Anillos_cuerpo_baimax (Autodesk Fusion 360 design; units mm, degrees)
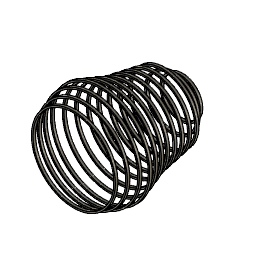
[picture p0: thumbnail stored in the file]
part number: 2026-07-18-00-39-53-117
parameter "d_1" = 112
parameter "d_1_int" = 108.5 (= "d_1 - 3.5 mm")
parameter "h_1" = -10
parameter "d_2" = 108.5
parameter "d_2_int" = 105 (= "d_2 - 3.5 mm")
parameter "h_2" = 10
parameter "h_3" = -20
parameter "h_4" = 20
parameter "h_5" = -30
parameter "h_6" = 30
parameter "h_7" = 40
parameter "d_3" = 105 (= "d_2_int")
parameter "d_3_int" = 101.5 (= "d_3 - 3.5 mm")
parameter "d_4" = 101.5 (= "d_3_int")
parameter "d_4_int" = 98 (= "d_4 - 3.5 mm")
parameter "d_5" = 98 (= "d_4_int")
parameter "d_5_int" = 94.5 (= "d_5 - 3.5 mm")
parameter "d_6" = 94.5 (= "d_5_int")
parameter "d_6_int" = 91 (= "d_6 - 3.5 mm")
parameter "d_7" = 91 (= "d_6_int")
parameter "d_7_int" = 87.5 (= "d_7 - 3.5 mm")
parameter "d_8" = 87.5 (= "d_7_int")
parameter "d_8_int" = 84 (= "d_8 - 3.5 mm")
parameter "h_8" = 50
parameter "h_9" = 60
parameter "h_10" = 70
parameter "h_11" = 110
parameter "h_12" = 120
parameter "h_13" = 130
parameter "h_14" = 140
parameter "h_15" = 80
parameter "d_9" = 84 (= "d_8_int")
parameter "d_9_int" = 80.5 (= "d_9 - 3.5 mm")
parameter "d_10" = 80.5 (= "d_9_int")
parameter "d_10_int" = 77 (= "d_10 - 3.5 mm")
parameter "d_11" = 77 (= "d_10_int")
parameter "d_11_int" = 73.5 (= "d_11 - 3.5 mm")
parameter "d_12" = 73.5 (= "d_11_int")
parameter "d_12_int" = 70 (= "d_12 - 3.5 mm")
parameter "d_13" = 70 (= "d_12_int")
parameter "d_13_int" = 66.5 (= "d_13 - 3.5 mm")
parameter "d_14" = 66.5 (= "d_13_int")
parameter "d_14_int" = 63 (= "d_14 - 3.5 mm")
parameter "d_15" = 63 (= "d_14_int")
parameter "d_15_int" = 59.5 (= "d_15 - 3.5 mm")
parameter "d_16" = 59.5 (= "d_15_int")
parameter "d_16_int" = 56 (= "d_16 - 3.5 mm")
parameter "h_16" = 160
parameter "h_17" = 170
parameter "h_18" = 180
parameter "h_19" = 90
parameter "h_20" = 200
parameter "d_17" = 56 (= "d_16_int")
parameter "d_17_int" = 52.5 (= "d_17 - 3.5 mm")
parameter "d_18" = 52.5 (= "d_17_int")
parameter "d_18_int" = 49 (= "d_18 - 3.5 mm")
parameter "d_19" = 49 (= "d_18_int")
parameter "d_19_int" = 45.5 (= "d_19 - 3.5 mm")
parameter "d_20" = 45.5 (= "d_19_int")
parameter "d_20_int" = 42 (= "d_20 - 3.5 mm")
parameter "d_21" = 42 (= "d_20_int")
parameter "d_21_int" = 38.5 (= "d_21 - 3.5 mm")
parameter "h_21" = 210
parameter "h_22" = 220
parameter "h_23" = 295
parameter "h_24" = 295
parameter "h_25" = 300
parameter "h_26" = 290
parameter "h_27" = 305
parameter "h_28" = 285
parameter "d_22" = 38.5 (= "d_21_int")
parameter "d_22_int" = 35 (= "d_22 - 3.5 mm")
parameter "d_23" = 35 (= "d_22_int")
parameter "d_23_int" = 31.5 (= "d_23 - 3.5 mm")
parameter "d_24" = 31.5 (= "d_23_int")
parameter "d_24_int" = 28 (= "d_24 - 3.5 mm")
parameter "d_25" = 28 (= "d_24_int")
parameter "d_25_int" = 24.5 (= "d_25 - 3.5 mm")
parameter "d_26" = 24.5 (= "d_25_int")
parameter "d_26_int" = 21 (= "d_26 - 3.5 mm")
parameter "d_27" = 21 (= "d_26_int")
parameter "d_27_int" = 17.5 (= "d_27 - 3.5 mm")
parameter "d_28" = 17.5 (= "d_27_int")
parameter "d_28_int" = 14 (= "d_28 - 3.5 mm")
parameter "d_29" = 14 (= "d_28_int")
parameter "d_29_int" = 10.5 (= "d_29 - 3.5 mm")
sketch "Boceto1" plane through (0, 0, 0) normal (0, 1, 0) x axis (1, 0, 0)
  circle C1 centre (0, 0) radius 56
  circle C2 centre (0, 0) radius 54.25
  point P1 (0, 0)
  point P2 (0, 0)
  coincident P1 P2
  concentric C1 C2
  dimension "d1" diameter C1 = 112 (= "d_1")
  dimension "d2" diameter C2 = 108.5 (= "d_1_int")
extrude "Extruir1" new body sketch "Boceto1" along normal blind 3
work_plane "PlanoDeObra2" AlongDistance -10 (= "h_1")
sketch "Boceto3" plane through (0, -10, 0) normal (0, 1, 0) x axis (1, 0, 0)
  circle C1 centre (0, 0) radius 54.25
  circle C2 centre (0, 0) radius 52.5
  point P1 (0, 0)
  point P2 (0, 0)
  coincident P1 P2
  concentric C1 C2
  dimension "d12" diameter C2 = 105 (= "d_2_int")
  dimension "d13" diameter C1 = 108.5 (= "d_2")
extrude "Extruir2" new body sketch "Boceto3" along normal blind 3
work_plane "PlanoDeObra3" AlongDistance 0
work_plane "PlanoDeObra4" AlongDistance 10 (= "h_2")
sketch "Boceto4" plane through (0, 10, 0) normal (0, 1, 0) x axis (1, 0, 0)
  circle C1 centre (0, 0) radius 52.5
  circle C2 centre (0, 0) radius 50.75
  point P1 (0, 0)
  point P2 (0, 0)
  point P3 (0, 0)
  coincident P1 P2
  coincident P1 P3
  dimension "d26" diameter C1 = 105 (= "d_3")
  dimension "d27" diameter C2 = 101.5 (= "d_3_int")
extrude "Extruir3" new body sketch "Boceto4" along normal blind 3
work_plane "PlanoDeObra5" AlongDistance -20 (= "h_3")
sketch "Boceto5" plane through (0, -20, 0) normal (0, 1, 0) x axis (1, 0, 0)
  circle C1 centre (0, 0) radius 50.75
  circle C2 centre (0, 0) radius 49
  point P1 (0, 0)
  point P2 (0, 0)
  point P3 (0, 0)
  coincident P1 P2
  coincident P1 P3
  dimension "d41" diameter C1 = 101.5 (= "d_4")
  dimension "d42" diameter C2 = 98 (= "d_4_int")
extrude "Extruir4" new body sketch "Boceto5" along normal blind 3
work_plane "PlanoDeObra6" AlongDistance 20 (= "h_4")
sketch "Boceto6" plane through (0, 20, 0) normal (0, 1, 0) x axis (1, 0, 0)
  circle C1 centre (0, 0) radius 49
  circle C2 centre (0, 0) radius 47.25
  point P1 (0, 0)
  point P2 (0, 0)
  coincident P1 P2
  concentric C1 C2
  dimension "d46" diameter C1 = 98 (= "d_5")
  dimension "d47" diameter C2 = 94.5 (= "d_5_int")
extrude "Extruir5" new body sketch "Boceto6" along normal blind 3
work_plane "PlanoDeObra7" AlongDistance -30 (= "h_5")
sketch "Boceto7" plane through (0, -30, 0) normal (0, 1, 0) x axis (1, 0, 0)
  circle C1 centre (0, 0) radius 47.25
  circle C2 centre (0, 0) radius 45.5
  point P1 (0, 0)
  point P2 (0, 0)
  coincident P1 P2
  concentric C1 C2
  dimension "d51" diameter C1 = 94.5 (= "d_6")
  dimension "d52" diameter C2 = 91 (= "d_6_int")
extrude "Extruir6" new body sketch "Boceto7" along normal blind 3
work_plane "PlanoDeObra8" AlongDistance 30 (= "h_6")
sketch "Boceto9" plane through (0, 30, 0) normal (0, 1, 0) x axis (1, 0, 0)
  circle C1 centre (0, 0) radius 45.5
  circle C2 centre (0, 0) radius 43.75
  point P1 (0, 0)
  point P2 (0, 0)
  point P3 (0, 0)
  coincident P1 P2
  coincident P1 P3
  dimension "d56" diameter C1 = 91 (= "d_7")
  dimension "d57" diameter C2 = 87.5 (= "d_7_int")
extrude "Extruir7" new body sketch "Boceto9" along normal blind 3
work_plane "PlanoDeObra9" AlongDistance 40 (= "h_7")
sketch "Boceto10" plane through (0, 40, 0) normal (0, 1, 0) x axis (1, 0, 0)
  circle C1 centre (0, 0) radius 43.75
  circle C2 centre (0, 0) radius 42
  point P1 (0, 0)
  point P2 (0, 0)
  coincident P1 P2
  concentric C1 C2
  dimension "d61" diameter C1 = 87.5 (= "d_8")
  dimension "d62" diameter C2 = 84 (= "d_8_int")
extrude "Extruir8" new body sketch "Boceto10" along normal blind 3
work_plane "PlanoDeObra10" AlongDistance 50 (= "h_8")
sketch "Boceto11" plane through (0, 50, 0) normal (0, 1, 0) x axis (1, 0, 0)
  circle C1 centre (0, 0) radius 42
  circle C2 centre (0, 0) radius 40.25
  point P1 (0, 0)
  point P2 (0, 0)
  coincident P1 P2
  concentric C1 C2
  dimension "d90" diameter C1 = 84 (= "d_9")
  dimension "d91" diameter C2 = 80.5 (= "d_9_int")
extrude "Extruir9" new body sketch "Boceto11" along normal blind 3
work_plane "PlanoDeObra11" AlongDistance 60 (= "h_9")
sketch "Boceto12" plane through (0, 60, 0) normal (0, 1, 0) x axis (1, 0, 0)
  circle C1 centre (0, 0) radius 40.25
  circle C2 centre (0, 0) radius 38.5
  point P1 (0, 0)
  point P2 (0, 0)
  point P3 (0, 0)
  coincident P1 P2
  coincident P1 P3
  dimension "d95" diameter C1 = 80.5 (= "d_10")
  dimension "d96" diameter C2 = 77 (= "d_10_int")
extrude "Extruir10" new body sketch "Boceto12" along normal blind 3
work_plane "PlanoDeObra12" AlongDistance 70 (= "h_10")
sketch "Boceto13" plane through (0, 70, 0) normal (0, 1, 0) x axis (1, 0, 0)
  circle C1 centre (0, 0) radius 38.5
  circle C2 centre (0, 0) radius 36.75
  point P1 (0, 0)
  point P2 (0, 0)
  point P3 (0, 0)
  coincident P1 P2
  coincident P1 P3
  dimension "d100" diameter C1 = 77 (= "d_11")
  dimension "d101" diameter C2 = 73.5 (= "d_11_int")
extrude "Extruir11" new body sketch "Boceto13" along normal blind 3
work_plane "PlanoDeObra13" AlongDistance 110 (= "h_11")
sketch "Boceto14" plane through (0, 110, 0) normal (0, 1, 0) x axis (1, 0, 0)
  circle C1 centre (0, 0) radius 36.75
  circle C2 centre (0, 0) radius 35
  point P1 (0, 0)
  point P2 (0, 0)
  coincident P1 P2
  concentric C1 C2
  dimension "d105" diameter C1 = 73.5 (= "d_12")
  dimension "d106" diameter C2 = 70 (= "d_12_int")
work_plane "PlanoDeObra14" AlongDistance 120 (= "h_12")
sketch "Boceto15" plane through (0, 120, 0) normal (0, 1, 0) x axis (1, 0, 0)
  circle C1 centre (0, 0) radius 35
  circle C2 centre (0, 0) radius 33.25
  point P1 (0, 0)
  point P2 (0, 0)
  coincident P1 P2
  concentric C1 C2
  dimension "d110" diameter C1 = 70 (= "d_13")
  dimension "d111" diameter C2 = 66.5 (= "d_13_int")
work_plane "PlanoDeObra15" AlongDistance 130 (= "h_13")
sketch "Boceto16" plane through (0, 130, 0) normal (0, 1, 0) x axis (1, 0, 0)
  circle C1 centre (0, 0) radius 33.25
  circle C2 centre (0, 0) radius 31.5
  point P1 (0, 0)
  point P2 (0, 0)
  coincident P1 P2
  concentric C1 C2
  dimension "d115" diameter C1 = 66.5 (= "d_14")
  dimension "d116" diameter C2 = 63 (= "d_14_int")
work_plane "PlanoDeObra17" AlongDistance 140 (= "h_14")
sketch "Boceto17" plane through (0, 140, 0) normal (0, 1, 0) x axis (1, 0, 0)
  circle C1 centre (0, 0) radius 31.5
  circle C2 centre (0, 0) radius 29.75
  point P1 (0, 0)
  point P2 (0, 0)
  point P3 (0, 0)
  coincident P1 P2
  coincident P1 P3
  dimension "d121" diameter C1 = 63 (= "d_15")
  dimension "d122" diameter C2 = 59.5 (= "d_15_int")
work_plane "PlanoDeObra18" AlongDistance 80 (= "h_15")
sketch "Boceto18" plane through (0, 80, 0) normal (0, 1, 0) x axis (1, 0, 0)
  circle C1 centre (0, 0) radius 29.75
  circle C2 centre (0, 0) radius 28
  point P1 (0, 0)
  point P2 (0, 0)
  point P3 (0, 0)
  coincident P1 P2
  coincident P1 P3
  dimension "d126" diameter C1 = 59.5 (= "d_16")
  dimension "d127" diameter C2 = 56 (= "d_16_int")
extrude "Extruir16" new body sketch "Boceto18" along normal blind 3
work_plane "PlanoDeObra19" AlongDistance 160 (= "h_16")
sketch "Boceto19" plane through (0, 160, 0) normal (0, 1, 0) x axis (1, 0, 0)
  circle C1 centre (0, 0) radius 28
  circle C2 centre (0, 0) radius 26.25
  point P1 (0, 0)
  point P2 (0, 0)
  coincident P1 P2
  concentric C1 C2
  dimension "d162" diameter C1 = 56 (= "d_17")
  dimension "d163" diameter C2 = 52.5 (= "d_17_int")
work_plane "PlanoDeObra20" AlongDistance 170 (= "h_17")
sketch "Boceto20" plane through (0, 170, 0) normal (0, 1, 0) x axis (1, 0, 0)
  circle C1 centre (0, 0) radius 26.25
  circle C2 centre (0, 0) radius 24.5
  point P1 (0, 0)
  point P2 (0, 0)
  coincident P1 P2
  concentric C1 C2
  dimension "d167" diameter C1 = 52.5 (= "d_18")
  dimension "d168" diameter C2 = 49 (= "d_18_int")
work_plane "PlanoDeObra21" AlongDistance 180 (= "h_18")
sketch "Boceto21" plane through (0, 180, 0) normal (0, 1, 0) x axis (1, 0, 0)
  circle C1 centre (0, 0) radius 24.5
  circle C2 centre (0, 0) radius 22.75
  point P1 (0, 0)
  point P2 (0, 0)
  point P3 (0, 0)
  coincident P1 P2
  coincident P1 P3
  dimension "d172" diameter C1 = 49 (= "d_19")
  dimension "d173" diameter C2 = 45.5 (= "d_19_int")
work_plane "PlanoDeObra22" AlongDistance 90 (= "h_19")
sketch "Boceto22" plane through (0, 90, 0) normal (0, 1, 0) x axis (1, 0, 0)
  circle C1 centre (0, 0) radius 22.75
  circle C2 centre (0, 0) radius 21
  point P1 (0, 0)
  point P2 (0, 0)
  point P3 (0, 0)
  coincident P1 P2
  coincident P1 P3
  dimension "d177" diameter C1 = 45.5 (= "d_20")
  dimension "d178" diameter C2 = 42 (= "d_20_int")
extrude "Extruir20" new body sketch "Boceto22" along normal blind 3
work_plane "PlanoDeObra24" AlongDistance 200 (= "h_20")
sketch "Boceto24" plane through (0, 200, 0) normal (0, 1, 0) x axis (1, 0, 0)
  circle C1 centre (0, 0) radius 21
  circle C2 centre (0, 0) radius 19.25
  point P1 (0, 0)
  point P2 (0, 0)
  point P3 (0, 0)
  coincident P1 P2
  coincident P1 P3
  dimension "d187" diameter C1 = 42 (= "d_21")
  dimension "d188" diameter C2 = 38.5 (= "d_21_int")
work_plane "PlanoDeObra25" AlongDistance 210 (= "h_21")
sketch "Boceto25" plane through (0, 210, 0) normal (0, 1, 0) x axis (1, 0, 0)
  circle C1 centre (0, 0) radius 19.25
  circle C2 centre (0, 0) radius 17.5
  point P1 (0, 0)
  point P2 (0, 0)
  coincident P1 P2
  concentric C1 C2
  dimension "d220" diameter C1 = 38.5 (= "d_22")
  dimension "d221" diameter C2 = 35 (= "d_22_int")
work_plane "PlanoDeObra26" AlongDistance 220 (= "h_22")
sketch "Boceto26" plane through (0, 220, 0) normal (0, 1, 0) x axis (1, 0, 0)
  circle C1 centre (0, 0) radius 17.5
  circle C2 centre (0, 0) radius 15.75
  point P1 (0, 0)
  point P2 (0, 0)
  coincident P1 P2
  concentric C1 C2
  dimension "d225" diameter C1 = 35 (= "d_23")
  dimension "d226" diameter C2 = 31.5 (= "d_23_int")
work_plane "PlanoDeObra28" AlongDistance 295 (= "h_23")
sketch "Boceto27" plane through (0, 295, 0) normal (0, 1, 0) x axis (1, 0, 0)
  circle C1 centre (0, 0) radius 15.75
  circle C2 centre (0, 0) radius 14
  point P1 (0, 0)
  point P2 (0, 0)
  coincident P1 P2
  concentric C1 C2
  dimension "d231" diameter C1 = 31.5 (= "d_24")
  dimension "d232" diameter C2 = 28 (= "d_24_int")
work_plane "PlanoDeObra29" AlongDistance 295 (= "h_24")
sketch "Boceto28" plane through (0, 295, 0) normal (0, 1, 0) x axis (1, 0, 0)
  circle C1 centre (0, 0) radius 14
  circle C2 centre (0, 0) radius 12.25
  point P1 (0, 0)
  point P2 (0, 0)
  point P3 (0, 0)
  coincident P1 P2
  coincident P1 P3
  dimension "d236" diameter C1 = 28 (= "d_25")
  dimension "d237" diameter C2 = 24.5 (= "d_25_int")
work_plane "PlanoDeObra30" AlongDistance 300 (= "h_25")
sketch "Boceto29" plane through (0, 300, 0) normal (0, 1, 0) x axis (1, 0, 0)
  circle C1 centre (0, 0) radius 12.25
  circle C2 centre (0, 0) radius 10.5
  point P1 (0, 0)
  point P2 (0, 0)
  coincident P1 P2
  concentric C1 C2
  dimension "d241" diameter C1 = 24.5 (= "d_26")
  dimension "d242" diameter C2 = 21 (= "d_26_int")
work_plane "PlanoDeObra31" AlongDistance 290 (= "h_26")
sketch "Boceto30" plane through (0, 290, 0) normal (0, 1, 0) x axis (1, 0, 0)
  circle C1 centre (0, 0) radius 10.5
  circle C2 centre (0, 0) radius 8.75
  point P1 (0, 0)
  point P2 (0, 0)
  point P3 (0, 0)
  coincident P1 P2
  coincident P1 P3
  dimension "d246" diameter C1 = 21 (= "d_27")
  dimension "d247" diameter C2 = 17.5 (= "d_27_int")
work_plane "PlanoDeObra32" AlongDistance 305 (= "h_27")
sketch "Boceto31" plane through (0, 305, 0) normal (0, 1, 0) x axis (1, 0, 0)
  circle C1 centre (0, 0) radius 8.75
  circle C2 centre (0, 0) radius 7
  point P1 (0, 0)
  point P2 (0, 0)
  coincident P1 P2
  concentric C1 C2
  dimension "d251" diameter C1 = 17.5 (= "d_28")
  dimension "d252" diameter C2 = 14 (= "d_28_int")
work_plane "PlanoDeObra33" AlongDistance 285 (= "h_28")
sketch "Boceto32" plane through (0, 285, 0) normal (0, 1, 0) x axis (1, 0, 0)
  circle C1 centre (0, 0) radius 7
  circle C2 centre (0, 0) radius 5.25
  point P1 (0, 0)
  point P2 (0, 0)
  coincident P1 P2
  concentric C1 C2
  dimension "d256" diameter C1 = 14 (= "d_29")
  dimension "d257" diameter C2 = 10.5 (= "d_29_int")
sketch "Boceto33" plane through (0, 0, 0) normal (0, 0, 1) x axis (1, 0, 0)
  line L1 (47.25, -30) -> (45.5, -30)
  line L2 (45.5, -27) -> (47.25, -27)
  line L3 (50.75, -20) -> (49, -20)
  line L4 (49, -17) -> (50.75, -17)
  line L5 (54.25, -10) -> (52.5, -10)
  line L6 (52.5, -7) -> (54.25, -7)
  line L7 (56, 0) -> (54.25, 0)
  line L8 (54.25, 3) -> (56, 3)
  line L9 (52.5, 10) -> (50.75, 10)
  line L10 (50.75, 13) -> (52.5, 13)
  line L11 (49, 20) -> (47.25, 20)
  line L12 (47.25, 23) -> (49, 23)
  line L13 (45.5, 30) -> (43.75, 30)
  line L14 (43.75, 33) -> (45.5, 33)
  line L15 (43.75, 40) -> (42, 40)
  line L16 (42, 43) -> (43.75, 43)
  line L17 (42, 50) -> (40.25, 50)
  line L18 (40.25, 53) -> (42, 53)
  line L19 (40.25, 60) -> (38.5, 60)
  line L20 (38.5, 63) -> (40.25, 63)
  line L21 (38.5, 70) -> (36.75, 70)
  line L22 (36.75, 73) -> (38.5, 73)
  line L23 (29.75, 80) -> (28, 80)
  line L24 (28, 83) -> (29.75, 83)
  line L25 (22.75, 90) -> (21, 90)
  line L26 (21, 93) -> (22.75, 93)
  line L27 (45.5, -30) -> (47.25, -30)
  line L28 (45.5, -27) -> (45.5, -30)
  line L29 (49, -20) -> (50.75, -20)
  line L30 (49, -17) -> (49, -20)
  line L31 (50.75, -17) -> (49, -17)
  line L32 (52.5, -10) -> (54.25, -10)
  line L33 (52.5, -10) -> (54.25, -10)
  line L34 (52.5, -7) -> (52.5, -10)
  line L35 (54.25, 0) -> (56, 0)
  line L36 (54.25, 0) -> (56, 0)
  line L37 (54.25, 3) -> (54.25, 0)
  line L38 (50.75, 10) -> (52.5, 10)
  line L39 (50.75, 13) -> (50.75, 10)
  line L40 (47.25, 20) -> (49, 20)
  line L41 (43.75, 30) -> (45.5, 30)
  line L42 (43.75, 33) -> (43.75, 30)
  line L43 (42, 40) -> (43.75, 40)
  line L44 (42, 43) -> (42, 40)
  line L45 (40.25, 50) -> (42, 50)
  line L46 (38.5, 60) -> (40.25, 60)
  line L47 (38.5, 63) -> (40.25, 63)
  line L48 (36.75, 70) -> (38.5, 70)
  line L49 (36.75, 73) -> (36.75, 70)
  line L50 (38.5, 60) -> (38.5, 63)
  line L51 (40.25, 53) -> (40.25, 50)
  line L52 (38.5, 73) -> (36.75, 75)
  line L53 (28, 80) -> (29.75, 80)
  line L54 (29.75, 83) -> (28, 85)
  line L55 (21, 90) -> (22.75, 90)
  line L56 (21, 93) -> (21, 90)
  line L57 (28, 83) -> (28, 80)
  line L58 (47.25, 23) -> (47.25, 20)
  line L59 (17, 88) -> (17, 90)
  line L60 (41.5, -32) -> (41.5, -25)
  line L61 (2, 90) -> (2, 95)
  line L62 (17, 90) -> (2, 90)
  line L63 (2, 100) -> (2, 95)
  line L64 (5, 100) -> (2, 100)
  line L65 (5, 96) -> (5, 100)
  line L66 (41.5, -37) -> (41.5, -32)
  line L67 (44.5, -37) -> (41.5, -37)
  line L68 (45.5, -37) -> (44.5, -37)
  line L69 (47.25, -38.2302) -> (47.25, -30)
  line L70 (47.25, -37) -> (45.5, -37)
  arc A1 centre (-131.6173, -3.3783) radius 174.4624 clockwise from (17, 88) to (41.5, -25)
  arc A2 centre (-12.1249, 48.1252) radius 54.4955 clockwise from (22.75, 90) to (29.75, 83)
  arc A3 centre (19.2917, 57.9584) radius 24.3969 clockwise from (29.75, 80) to (38.5, 73)
  arc A4 centre (-26.7489, 49.969) radius 68.2544 clockwise from (38.5, 70) to (40.25, 63)
  arc A5 centre (-76.2927, 27.1457) radius 121.0852 clockwise from (40.25, 60) to (42, 53)
  arc A6 centre (22.875, 41.5) radius 20.9289 clockwise from (42, 50) to (43.75, 43)
  arc A7 centre (-1.5, 24.9688) radius 47.6812 clockwise from (43.75, 40) to (45.5, 33)
  arc A8 centre (19.0393, 12.3947) radius 31.7823 clockwise from (45.5, 30) to (49, 23)
  arc A9 centre (-15.6248, -16.6874) radius 74.3124 clockwise from (49, 20) to (52.5, 13)
  arc A10 centre (40.625, -0.3125) radius 15.7278 clockwise from (52.5, 10) to (56, 3)
  arc A11 centre (21.7396, 4.8464) radius 34.6015 clockwise from (56, 0) to (54.25, -7)
  arc A12 centre (24.9327, 0.2836) radius 31.0686 clockwise from (54.25, -10) to (50.75, -17)
  arc A13 centre (-15.8334, 8.9167) radius 72.5915 clockwise from (50.75, -20) to (47.25, -27)
  arc A14 centre (4.1403, 36.9029) radius 59.1033 clockwise from (5, 96) to (22.75, 93)
  point P52 (28, 85)
  point P50 (36.75, 75)
  point P84 (47.25, -37)
  point P2 (47.25, -30)
  point P3 (47.25, -27)
  point P28 (45.5, -30)
  point P8 (56, 0)
  point P35 (54.25, 0)
  point P10 (52.5, 10)
  point P37 (50.75, 10)
  point P12 (49, 20)
  point P39 (47.25, 20)
  point P14 (45.5, 30)
  point P40 (43.75, 30)
  point P18 (42, 50)
  point P44 (40.25, 50)
  point P22 (38.5, 70)
  point P47 (36.75, 70)
  horizontal L1
  perpendicular L2 L28
  perpendicular L4 L30
  perpendicular L6 L34
  perpendicular L8 L37
  perpendicular L10 L39
  perpendicular L14 L42
  perpendicular L16 L44
  perpendicular L22 L49
  perpendicular L19 L50
  perpendicular L18 L51
  perpendicular L26 L56
  perpendicular L24 L57
  perpendicular L12 L58
  coincident P52 A2
  coincident P50 A3
  perpendicular L59 L62
  perpendicular L63 L64
  perpendicular L66 L67
  perpendicular L27 L69
  coincident L69 P84
  perpendicular L69 L70
  dimension "d262" distance P2 P3 = 3
  dimension "d263" distance P2 P28 = 1.75
  dimension "d272" distance P8 P35 = 1.75
  dimension "d275" distance P10 P37 = 1.75
  dimension "d280" distance P12 P39 = 1.75
  dimension "d285" distance P14 P40 = 1.75
  dimension "d288" distance P18 P44 = 1.75
  dimension "d291" distance P22 P47 = 1.75
sketch "Boceto34" plane through (0, 93, 0) normal (0, 1, 0) x axis (-1, 0, 0)
  line L1 (-185, 110) -> (-160, 110)
  line L2 (-160, 85) -> (-160, 110)
  line L3 (-135, 110) -> (-160, 110)
  line L4 (-160, 135) -> (-160, 110)
  line L5 (-184.8747, 107.5) -> (-160, 107.5)
  line L6 (-184.8747, 112.5) -> (-160, 112.5)
  line L7 (-162.5, 85.1253) -> (-162.5, 110)
  line L8 (-157.5, 85.1253) -> (-157.5, 110)
  line L9 (-135.1253, 107.5) -> (-160, 107.5)
  line L10 (-135.1253, 112.5) -> (-160, 112.5)
  line L11 (-162.5, 134.8747) -> (-162.5, 110)
  line L12 (-157.5, 134.8747) -> (-157.5, 110)
  circle C1 centre (-160, 110) radius 21
  circle C2 centre (-160, 110) radius 22.75
  circle C3 centre (-160, 110) radius 21
  circle C4 centre (-160, 110) radius 2.5
  circle C5 centre (-160, 110) radius 22.75
  circle C6 centre (-160, 110) radius 25
  point P6 (-160, 110)
  point P7 (-160, 110)
  point P8 (-185, 110)
  point P3 (-160, 110)
  point P9 (-160, 110)
  point P10 (-160, 85)
  point P5 (-160, 110)
  point P11 (-160, 110)
  point P12 (-135, 110)
  point P13 (-160, 135)
  point P14 (-160, 107.5)
  point P15 (-184.8747, 107.5)
  point P16 (-160, 112.5)
  point P17 (-184.8747, 112.5)
  point P18 (-162.5, 110)
  point P19 (-162.5, 85.1253)
  point P20 (-157.5, 110)
  point P21 (-157.5, 85.1253)
  point P22 (-135.1253, 107.5)
  point P23 (-135.1253, 112.5)
  point P24 (-162.5, 134.8747)
  point P25 (-157.5, 134.8747)
  tangent C1 C3
  concentric C3 C4
  concentric C4 C5
  concentric C4 C6
  coincident P6 P7
  coincident C6 P8
  horizontal L1
  coincident P3 P9
  coincident C6 P10
  perpendicular L1 L2
  coincident P5 P11
  coincident C6 P12
  perpendicular L2 L3
  coincident C6 P13
  perpendicular L3 L4
  coincident C4 P14
  coincident L2 P14
  coincident C6 P15
  tangent C4 L5
  coincident C4 P16
  coincident L4 P16
  coincident C6 P17
  tangent C4 L6
  coincident C4 P18
  coincident L1 P18
  coincident C6 P19
  tangent C4 L7
  coincident C4 P20
  coincident L3 P20
  coincident C6 P21
  tangent C4 L8
  coincident C6 P22
  horizontal L9
  coincident C6 P23
  parallel L9 L10
  coincident C6 P24
  perpendicular L10 L11
  coincident C6 P25
  vertical L12
  dimension "d294" diameter C4 = 5
  dimension "d297" diameter C6 = 50
extrude "Extruir31" new body sketch "Boceto34" profile of C4 along normal blind 10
